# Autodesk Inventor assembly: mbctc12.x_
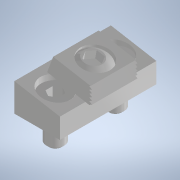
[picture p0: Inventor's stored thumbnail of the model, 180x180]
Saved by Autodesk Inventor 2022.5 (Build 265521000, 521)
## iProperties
Created: 2022-11
Part Number: mbctc12.x_
Document SubType Name: Assembly
Designer: ImaoCorp
Sending System: SOLIDWORKS 2020-2020296
MC: AMD64
MC_MODEL: Intel64 Family 6 Model 60 Stepping 3, GenuineIntel
OS: Windows_NT
FRU: Parasolid Version 31.1, build 290,  3- 9-2020
FORMAT: text
GUISE: transmit
KEY: mbctc12
FILE: mbctc12.x_t
DATE: Thu Nov 24 16:35:16 2022
Author: ImaoCorp
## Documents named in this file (6)
- X:\14_SW2022-Inv2022\00_全2023-1023新製品(TCC)まで\m\mbctc12\MBCTC12.iam
- X:\14_SW2022-Inv2022\00_全2023-1023新製品(TCC)まで\m\mbctc12\mbctc12_01.ipt
- X:\14_SW2022-Inv2022\00_全2023-1023新製品(TCC)まで\m\mbctc12\mbctc12_02.ipt
- X:\14_SW2022-Inv2022\00_全2023-1023新製品(TCC)まで\m\mbctc12\mbctc12_03.ipt
- X:\14_SW2022-Inv2022\00_全2023-1023新製品(TCC)まで\m\mbctc12\mbctc12_04.ipt
- X:\14_SW2022-Inv2022\00_全2023-1023新製品(TCC)まで\m\mbctc12\mbctc12_05.ipt
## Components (5 placed, 5 different names)
1. mbctc12_01
2. mbctc12_02
3. mbctc12_03
4. mbctc12_04
5. mbctc12_05
